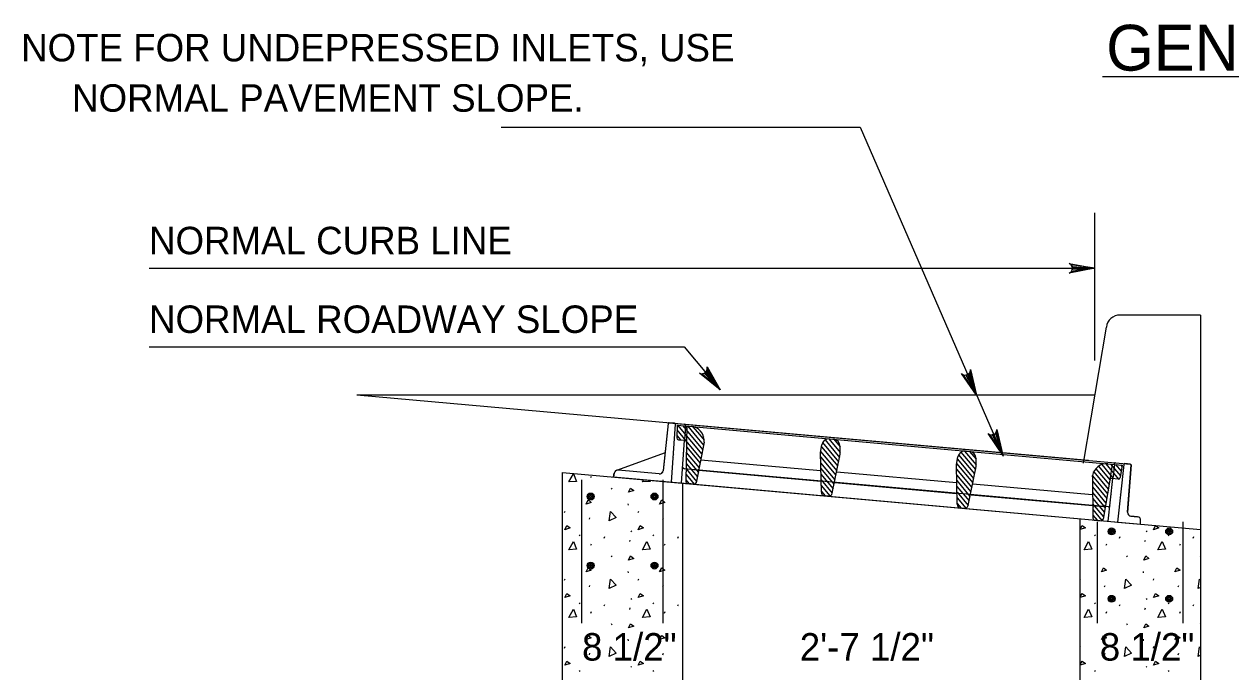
# Model space of a CAD drawing. Extents: x 6.91 to 13.84, y 0.35 to 9.99.
# Drawn here: x 6.908 to 9.548, y 3.739 to 5.155 of the extents above; entities that cross this region are included whole.
import ezdxf

# ---------------------------------------------------------------- set-up
doc = ezdxf.new("R2010")
doc.units = 0
for name, color, linetype in [('Default', 7, 'Continuous'), ('DETL-DIMS', 7, 'Continuous'), ('DETL-LINE', 7, 'Continuous'), ('DETL-NOTE', 7, 'Continuous')]:
    doc.layers.add(name, color=color, linetype=linetype)

msp = doc.modelspace()

# ---------------------------------------------------------------- linework, layer by layer
at = {"layer": 'Default'}
for p, q in [((8.1477, 4.1641), (8.1493, 4.1673)), ((8.2609, 4.1544), (8.2636, 4.1595)), ((8.1924, 4.1411), (8.194, 4.1387)), ((8.2287, 4.1069), (8.2291, 4.1037)), ((8.0902, 4.0876), (8.0914, 4.0908)), ((8.1445, 4.0731), (8.1457, 4.0763)), ((8.2512, 4.0876), (8.2524, 4.0908)), ((8.3055, 4.0731), (8.3068, 4.0763)), ((8.2355, 4.0477), (8.2367, 4.0457)), ((9.3627, 4.0477), (9.3639, 4.0457)), ((8.1224, 4.0385), (8.124, 4.0365)), ((8.1477, 4.0159), (8.1493, 4.0192)), ((8.1767, 4.0316), (8.1783, 4.0349)), ((8.2327, 4.024), (8.2339, 4.0272)), ((8.2834, 4.0385), (8.285, 4.0365)), ((8.3088, 4.0159), (8.3104, 4.0192)), ((8.3378, 4.0316), (8.3394, 4.0349)), ((9.2496, 4.0385), (9.2512, 4.0365)), ((9.2749, 4.0159), (9.2766, 4.0192)), ((9.3039, 4.0316), (9.3055, 4.0349)), ((9.3599, 4.024), (9.3611, 4.0272)), ((9.4106, 4.0385), (9.4122, 4.0365)), ((9.436, 4.0159), (9.4376, 4.0192)), ((9.465, 4.0316), (9.4666, 4.0349)), ((8.1924, 3.993), (8.194, 3.9906)), ((9.3196, 3.993), (9.3212, 3.9906)), ((9.4807, 3.993), (9.4813, 3.992)), ((8.0902, 3.9394), (8.0914, 3.9427)), ((8.2287, 3.9588), (8.2291, 3.9555)), ((8.2512, 3.9394), (8.2524, 3.9427)), ((9.2184, 3.9421), (9.2186, 3.9427)), ((9.3559, 3.9588), (9.3563, 3.9555)), ((9.3784, 3.9394), (9.3796, 3.9427)), ((8.1445, 3.9249), (8.1457, 3.9282)), ((8.3055, 3.9249), (8.3068, 3.9282)), ((9.2717, 3.9249), (9.2729, 3.9282)), ((9.4328, 3.9249), (9.434, 3.9282)), ((9.4813, 3.9237), (9.4762, 3.9213)), ((8.1224, 3.8903), (8.124, 3.8883)), ((8.1767, 3.8835), (8.1783, 3.8867)), ((8.2355, 3.8996), (8.2367, 3.8976)), ((8.2834, 3.8903), (8.285, 3.8883)), ((8.3378, 3.8835), (8.3394, 3.8867)), ((9.2496, 3.8903), (9.2512, 3.8883)), ((9.3039, 3.8835), (9.3055, 3.8867)), ((9.3627, 3.8996), (9.3639, 3.8976)), ((9.4106, 3.8903), (9.4122, 3.8883)), ((9.465, 3.8835), (9.4666, 3.8867)), ((8.1477, 3.8678), (8.1493, 3.871)), ((8.2327, 3.8758), (8.2339, 3.8791)), ((8.3088, 3.8678), (8.3104, 3.871)), ((9.2749, 3.8678), (9.2766, 3.871)), ((9.3599, 3.8758), (9.3611, 3.8791)), ((9.436, 3.8678), (9.4376, 3.871)), ((8.1924, 3.8448), (8.194, 3.8424)), ((9.3196, 3.8448), (9.3212, 3.8424)), ((9.4807, 3.8448), (9.4813, 3.8439)), ((8.2287, 3.8106), (8.2291, 3.8074)), ((9.3559, 3.8106), (9.3563, 3.8074)), ((8.0902, 3.7913), (8.0914, 3.7945)), ((8.1445, 3.7768), (8.1457, 3.78)), ((8.2512, 3.7913), (8.2524, 3.7945)), ((8.3055, 3.7768), (8.3068, 3.78)), ((9.2184, 3.794), (9.2186, 3.7945)), ((9.2717, 3.7768), (9.2729, 3.78)), ((9.3784, 3.7913), (9.3796, 3.7945)), ((9.4328, 3.7768), (9.434, 3.78)), ((9.4813, 3.7756), (9.4762, 3.7732)), ((8.2355, 3.7514), (8.2367, 3.7494)), ((9.3627, 3.7514), (9.3639, 3.7494)), ((8.1224, 3.7422), (8.124, 3.7402)), ((8.2834, 3.7422), (8.285, 3.7402)), ((9.2496, 3.7422), (9.2512, 3.7402)), ((9.4106, 3.7422), (9.4122, 3.7402))]:
    msp.add_line(p, q, dxfattribs=at)
for points in [[(8.0998, 4.1544), (8.1095, 4.1725), (8.1167, 4.1556), (8.0998, 4.1544)], [(8.2766, 4.1583), (8.2778, 4.1556), (8.2609, 4.1544)], [(8.2303, 4.1319), (8.2343, 4.1407), (8.2415, 4.1355), (8.2303, 4.1319)], [(8.1373, 4.1061), (8.1417, 4.115), (8.1485, 4.1097), (8.1373, 4.1061)], [(8.2983, 4.1061), (8.3027, 4.115), (8.3096, 4.1097), (8.2983, 4.1061)], [(8.188, 4.0695), (8.1908, 4.09), (8.2033, 4.0767), (8.188, 4.0695)], [(8.0906, 4.0501), (8.095, 4.059), (8.1022, 4.0538), (8.0906, 4.0501)], [(8.2516, 4.0501), (8.256, 4.059), (8.2633, 4.0538), (8.2516, 4.0501)], [(9.2184, 4.0513), (9.2222, 4.059), (9.2295, 4.0538), (9.2184, 4.0503)], [(9.3788, 4.0501), (9.3832, 4.059), (9.3905, 4.0538), (9.3788, 4.0501)], [(8.0998, 4.0063), (8.1095, 4.0244), (8.1167, 4.0075), (8.0998, 4.0063)], [(8.2609, 4.0063), (8.2705, 4.0244), (8.2778, 4.0075), (8.2609, 4.0063)], [(9.227, 4.0063), (9.2367, 4.0244), (9.2439, 4.0075), (9.227, 4.0063)], [(9.3881, 4.0063), (9.3977, 4.0244), (9.405, 4.0075), (9.3881, 4.0063)], [(8.2303, 3.9837), (8.2343, 3.9926), (8.2415, 3.9873), (8.2303, 3.9837)], [(9.3575, 3.9837), (9.3615, 3.9926), (9.3687, 3.9873), (9.3575, 3.9837)], [(8.1373, 3.958), (8.1417, 3.9668), (8.1485, 3.9616), (8.1373, 3.958)], [(8.2983, 3.958), (8.3027, 3.9668), (8.3096, 3.9616), (8.2983, 3.958)], [(9.2645, 3.958), (9.2689, 3.9668), (9.2757, 3.9616), (9.2645, 3.958)], [(9.4255, 3.958), (9.4299, 3.9668), (9.4368, 3.9616), (9.4255, 3.958)], [(8.188, 3.9213), (8.1908, 3.9419), (8.2033, 3.9286), (8.188, 3.9213)], [(9.3152, 3.9213), (9.318, 3.9419), (9.3305, 3.9286), (9.3152, 3.9213)], [(9.4762, 3.9213), (9.479, 3.9419), (9.4813, 3.9394)], [(8.0906, 3.902), (8.095, 3.9109), (8.1022, 3.9056), (8.0906, 3.902)], [(8.2516, 3.902), (8.256, 3.9109), (8.2633, 3.9056), (8.2516, 3.902)], [(9.2184, 3.9032), (9.2222, 3.9109), (9.2295, 3.9056), (9.2184, 3.9022)], [(9.3788, 3.902), (9.3832, 3.9109), (9.3905, 3.9056), (9.3788, 3.902)], [(8.0998, 3.8581), (8.1095, 3.8762), (8.1167, 3.8593), (8.0998, 3.8581)], [(8.2609, 3.8581), (8.2705, 3.8762), (8.2778, 3.8593), (8.2609, 3.8581)], [(9.227, 3.8581), (9.2367, 3.8762), (9.2439, 3.8593), (9.227, 3.8581)], [(9.3881, 3.8581), (9.3977, 3.8762), (9.405, 3.8593), (9.3881, 3.8581)], [(8.2303, 3.8356), (8.2343, 3.8444), (8.2415, 3.8392), (8.2303, 3.8356)], [(9.3575, 3.8356), (9.3615, 3.8444), (9.3687, 3.8392), (9.3575, 3.8356)], [(8.1373, 3.8098), (8.1417, 3.8187), (8.1485, 3.8134), (8.1373, 3.8098)], [(8.2983, 3.8098), (8.3027, 3.8187), (8.3096, 3.8134), (8.2983, 3.8098)], [(9.2645, 3.8098), (9.2689, 3.8187), (9.2757, 3.8134), (9.2645, 3.8098)], [(9.4255, 3.8098), (9.4299, 3.8187), (9.4368, 3.8134), (9.4255, 3.8098)], [(8.188, 3.7732), (8.1908, 3.7937), (8.2033, 3.7804), (8.188, 3.7732)], [(9.3152, 3.7732), (9.318, 3.7937), (9.3305, 3.7804), (9.3152, 3.7732)], [(9.4762, 3.7732), (9.479, 3.7937), (9.4813, 3.7913)], [(8.0906, 3.7539), (8.095, 3.7627), (8.1022, 3.7575), (8.0906, 3.7539)], [(8.2516, 3.7539), (8.256, 3.7627), (8.2633, 3.7575), (8.2516, 3.7539)], [(9.2184, 3.7551), (9.2222, 3.7627), (9.2295, 3.7575), (9.2184, 3.754)], [(9.3788, 3.7539), (9.3832, 3.7627), (9.3905, 3.7575), (9.3788, 3.7539)]]:
    msp.add_lwpolyline(points, dxfattribs=at)
at = {"layer": 'DETL-DIMS'}
for p, q in [((7.9515, 4.9299), (8.737, 4.9299)), ((8.737, 4.9299), (9.0498, 4.2111)), ((9.2505, 4.42), (9.2505, 4.7428)), ((7.1813, 4.6215), (9.2505, 4.6215)), ((7.1813, 4.4494), (8.3517, 4.4494)), ((8.3517, 4.4494), (8.4303, 4.356))]:
    msp.add_line(p, q, dxfattribs=at)
for points in [[(9.2505, 4.6215), (9.194, 4.6109), (9.1983, 4.6139), (9.2006, 4.6177), (9.2012, 4.6215), (9.2006, 4.6253), (9.1983, 4.629), (9.194, 4.6321), (9.2505, 4.6215), (9.1983, 4.629), (9.2006, 4.6253), (9.2505, 4.6215), (9.2012, 4.6215), (9.2006, 4.6177), (9.2505, 4.6215), (9.1983, 4.6139)], [(8.4303, 4.356), (8.3858, 4.3924), (8.3909, 4.391), (8.3953, 4.3918), (8.3986, 4.3937), (8.4011, 4.3966), (8.4025, 4.4008), (8.402, 4.4061), (8.4303, 4.356), (8.4025, 4.4008), (8.4011, 4.3966), (8.4303, 4.356), (8.3986, 4.3937), (8.3953, 4.3918), (8.4303, 4.356), (8.3909, 4.391)], [(8.9911, 4.3438), (8.9588, 4.3914), (8.9633, 4.3886), (8.9677, 4.3881), (8.9714, 4.389), (8.9746, 4.3911), (8.9772, 4.3947), (8.9783, 4.3999), (8.9911, 4.3438), (8.9772, 4.3947), (8.9746, 4.3911), (8.9911, 4.3438), (8.9714, 4.389), (8.9677, 4.3881), (8.9911, 4.3438), (8.9633, 4.3886)], [(9.0491, 4.2128), (9.0168, 4.2605), (9.0213, 4.2577), (9.0257, 4.2571), (9.0294, 4.258), (9.0326, 4.2601), (9.0352, 4.2637), (9.0362, 4.2689), (9.0491, 4.2128), (9.0352, 4.2637), (9.0326, 4.2601), (9.0491, 4.2128), (9.0294, 4.258), (9.0257, 4.2571), (9.0491, 4.2128), (9.0213, 4.2577)]]:
    msp.add_lwpolyline(points, dxfattribs=at)
at = {"layer": 'DETL-LINE'}
for p, q in [((9.4813, 4.5192), (9.3055, 4.5192)), ((9.4813, 4.5192), (9.4813, 2.6989)), ((9.2256, 4.1954), (9.2755, 4.4929)), ((7.6359, 4.3449), (9.2364, 4.202)), ((7.6359, 4.3449), (9.2506, 4.3449)), ((8.317, 4.2822), (8.3057, 4.1789)), ((8.317, 4.2822), (8.3058, 4.1791)), ((8.3309, 4.2829), (8.3191, 4.2839)), ((8.3191, 4.2839), (9.3277, 4.1936)), ((8.3242, 4.1539), (8.3327, 4.2808)), ((8.3376, 4.2783), (8.3681, 4.2419)), ((8.3487, 4.2773), (8.3738, 4.2473)), ((8.355, 4.2768), (8.3529, 4.2456)), ((8.355, 4.2768), (8.3552, 4.2788)), ((8.3576, 4.2765), (8.3568, 4.2416)), ((8.3358, 4.2561), (8.344, 4.2464)), ((8.3361, 4.268), (8.3624, 4.2365)), ((8.3597, 4.2764), (8.3795, 4.2526)), ((8.3709, 4.2751), (8.3852, 4.258)), ((8.3795, 4.2526), (8.3944, 4.2348)), ((8.3852, 4.258), (8.3957, 4.2455)), ((8.3464, 4.152), (8.3529, 4.2456)), ((8.3567, 4.2312), (8.3867, 4.1952)), ((8.3624, 4.2365), (8.3886, 4.2051)), ((8.3681, 4.2419), (8.3905, 4.215)), ((8.3738, 4.2473), (8.3925, 4.2249)), ((8.6522, 4.2311), (8.6877, 4.1886)), ((8.6546, 4.2404), (8.6897, 4.1984)), ((8.66, 4.2461), (8.6917, 4.2082)), ((8.6682, 4.2486), (8.6931, 4.2187)), ((8.679, 4.2477), (8.6931, 4.2309)), ((8.31, 4.218), (8.2042, 4.1796)), ((8.3564, 4.2071), (8.3829, 4.1754)), ((8.3565, 4.2191), (8.3848, 4.1853)), ((8.6502, 4.2091), (8.6837, 4.1691)), ((8.6504, 4.2211), (8.6857, 4.1788)), ((8.9496, 4.2045), (8.9851, 4.162)), ((8.952, 4.2137), (8.9871, 4.1718)), ((8.9574, 4.2195), (8.9891, 4.1815)), ((8.9655, 4.2219), (8.9905, 4.192)), ((8.9764, 4.2211), (8.9905, 4.2042)), ((8.0857, 2.6989), (8.0857, 4.1753)), ((8.0857, 4.1753), (9.4813, 4.0507)), ((8.1976, 4.1653), (8.1991, 4.1737)), ((8.2973, 4.172), (8.2075, 4.1801)), ((8.2973, 4.172), (8.2075, 4.1801)), ((8.3598, 4.1822), (8.3523, 4.1828)), ((8.356, 4.171), (8.374, 4.1495)), ((8.3562, 4.183), (8.379, 4.1556)), ((8.3563, 4.195), (8.3809, 4.1655)), ((9.2696, 4.1007), (8.3598, 4.1822)), ((8.3802, 4.1803), (8.3598, 4.1822)), ((8.6505, 4.1965), (8.6817, 4.1593)), ((8.6508, 4.184), (8.6796, 4.1495)), ((8.6511, 4.1714), (8.6776, 4.1397)), ((8.9476, 4.1824), (8.981, 4.1424)), ((8.9478, 4.1944), (8.9831, 4.1522)), ((9.248, 4.1765), (9.2797, 4.1386)), ((9.2525, 4.1833), (9.2814, 4.1488)), ((9.2583, 4.1886), (9.2831, 4.1588)), ((9.2654, 4.1923), (9.2911, 4.1615)), ((9.2741, 4.1941), (9.302, 4.1607)), ((9.2885, 4.1932), (9.2831, 4.1586)), ((9.2848, 4.1935), (9.3061, 4.168)), ((9.2933, 4.1927), (9.2899, 4.1616)), ((9.2933, 4.1927), (9.2935, 4.1947)), ((9.2958, 4.1925), (9.3077, 4.1782)), ((9.3138, 4.1929), (9.2996, 4.0666)), ((9.3138, 4.1929), (9.2996, 4.0666)), ((9.3068, 4.1915), (9.3093, 4.1885)), ((9.3277, 4.1936), (9.3159, 4.1946)), ((9.322, 4.0881), (9.3294, 4.1915)), ((9.3294, 4.1915), (9.322, 4.0879)), ((8.1281, 3.8456), (8.1281, 4.1591)), ((8.1976, 4.1653), (9.3502, 4.062)), ((8.3063, 3.8456), (8.3063, 4.1591)), ((8.3487, 2.8202), (8.3487, 4.1519)), ((8.3559, 4.1589), (8.363, 4.1505)), ((8.6514, 4.1589), (8.6756, 4.1299)), ((8.6517, 4.1463), (8.6706, 4.1237)), ((8.9479, 4.1698), (8.979, 4.1326)), ((8.9482, 4.1573), (8.977, 4.1228)), ((8.9485, 4.1447), (8.975, 4.113)), ((9.2449, 4.1558), (9.2762, 4.1183)), ((9.2451, 4.1677), (9.2779, 4.1285)), ((9.2797, 4.0684), (9.2899, 4.1616)), ((8.652, 4.1338), (8.6603, 4.1238)), ((8.9488, 4.1322), (8.973, 4.1032)), ((8.9491, 4.1196), (8.9679, 4.0971)), ((9.2451, 4.1434), (9.2745, 4.1082)), ((9.2452, 4.1311), (9.2728, 4.0981)), ((9.2454, 4.1187), (9.2711, 4.0879)), ((8.9494, 4.1071), (8.9577, 4.0972)), ((9.2452, 4.1028), (9.2491, 4.1025)), ((9.2455, 4.1063), (9.2694, 4.0778)), ((9.2457, 4.0939), (9.2658, 4.0699)), ((9.2491, 4.1025), (9.2696, 4.1007)), ((9.2793, 4.0998), (9.2696, 4.1007)), ((9.2184, 2.8202), (9.2184, 4.0742)), ((9.2459, 4.0815), (9.255, 4.0706)), ((9.256, 3.8456), (9.256, 4.067)), ((9.3433, 4.0784), (9.3291, 4.0796)), ((9.3291, 4.0796), (9.3433, 4.0784)), ((9.3502, 4.062), (9.3504, 4.0704)), ((9.4437, 3.8456), (9.4437, 4.067))]:
    msp.add_line(p, q, dxfattribs=at)
for points in [[(8.1991, 4.1737), (8.1976, 4.1653), (8.3242, 4.1539), (8.3327, 4.2808)], [(9.2996, 4.0666), (9.3502, 4.062), (9.3504, 4.0704)]]:
    msp.add_lwpolyline(points, dxfattribs=at)
for centre, radius in [((8.1474, 4.1226), 0.00758), ((8.1474, 4.1226), 0.00569), ((8.1474, 4.1226), 0.00379), ((8.1474, 4.1226), 0.0019), ((8.287, 4.1226), 0.00758), ((8.287, 4.1226), 0.00569), ((8.287, 4.1226), 0.00379), ((8.287, 4.1226), 0.0019), ((9.2869, 4.0462), 0.00758), ((9.2869, 4.0462), 0.00569), ((9.2869, 4.0462), 0.00379), ((9.2869, 4.0462), 0.0019), ((9.4128, 4.0462), 0.00758), ((9.4128, 4.0462), 0.00569), ((9.4128, 4.0462), 0.00379), ((9.4128, 4.0462), 0.0019), ((8.1474, 3.9717), 0.00758), ((8.1474, 3.9717), 0.00569), ((8.1474, 3.9717), 0.00379), ((8.1474, 3.9717), 0.0019), ((8.287, 3.9717), 0.00758), ((8.287, 3.9717), 0.00569), ((8.287, 3.9717), 0.00379), ((8.287, 3.9717), 0.0019), ((9.2869, 3.899), 0.00758), ((9.2869, 3.899), 0.00569), ((9.2869, 3.899), 0.00379), ((9.2869, 3.899), 0.0019), ((9.4128, 3.899), 0.00758), ((9.4128, 3.899), 0.00569), ((9.4128, 3.899), 0.00379), ((9.4128, 3.899), 0.0019)]:
    msp.add_circle(centre, radius, dxfattribs=at)
for centre, radius, start, end in [((9.3055, 4.4888), 0.0303, 90, 172.2341), ((8.3189, 4.282), 0.00195, 84.8815, 173.7719), ((8.3189, 4.282), 0.00195, 84.8815, 173.7719), ((8.3307, 4.2809), 0.00195, 356.1793, 84.8815), ((8.3307, 4.2809), 0.00195, 356.1793, 84.8815), ((8.3532, 4.2789), 0.00195, 356.0273, 84.8815), ((8.2068, 4.1723), 0.00782, 84.8755, 169.8815), ((8.2068, 4.1723), 0.00782, 84.8815, 169.8815), ((8.298, 4.1798), 0.00782, 264.8755, 354.4477), ((8.298, 4.1798), 0.00782, 264.8815, 353.0961), ((8.3527, 4.1867), 0.00391, 176.0273, 264.8815), ((8.3601, 4.186), 0.00391, 178.6956, 264.8815), ((8.3806, 4.1842), 0.00391, 264.8815, 349.8815), ((9.2955, 4.1945), 0.00195, 84.8815, 173.7484), ((9.3157, 4.1927), 0.00195, 84.8815, 173.5837), ((9.3157, 4.1927), 0.00195, 84.8815, 173.5837), ((9.3275, 4.1916), 0.00195, 355.8908, 84.8815), ((9.3275, 4.1916), 0.00195, 355.8908, 84.8815), ((9.2495, 4.1064), 0.00391, 179.8815, 264.8815), ((9.2699, 4.1045), 0.00391, 264.8815, 351.0675), ((9.2796, 4.1037), 0.00391, 264.8815, 353.7358), ((9.3298, 4.0874), 0.00782, 175.1145, 264.8815), ((9.3298, 4.0874), 0.00782, 176.667, 264.8815), ((9.3426, 4.0706), 0.00782, 358.4238, 84.8815), ((9.3426, 4.0706), 0.00782, 358.4238, 84.8815)]:
    msp.add_arc(centre, radius, start, end, dxfattribs=at)
at = {"layer": 'DETL-NOTE'}
for p, q in [((9.2669, 5.0407), (10.5175, 5.0407)), ((8.3363, 4.2784), (8.3357, 4.2508)), ((8.3363, 4.2784), (9.3097, 4.1913)), ((8.3363, 4.2784), (8.3363, 4.2784)), ((8.3968, 4.2537), (8.3968, 4.2537)), ((8.3393, 4.2468), (8.3532, 4.2455)), ((8.3393, 4.2468), (8.3393, 4.2468)), ((8.3568, 4.2416), (8.3559, 4.1548)), ((8.3957, 4.2417), (8.3784, 4.1527)), ((8.3957, 4.2417), (8.3957, 4.2445)), ((8.65, 4.219), (8.653, 4.2358)), ((8.6931, 4.2151), (8.6931, 4.2322)), ((8.329, 4.2079), (8.329, 4.2079)), ((8.3305, 4.2135), (8.3305, 4.2135)), ((8.3491, 4.2117), (8.3491, 4.2117)), ((8.3524, 4.2183), (8.3524, 4.2183)), ((8.3882, 4.2031), (8.6503, 4.1797)), ((8.6521, 4.1318), (8.65, 4.219)), ((8.6756, 4.1297), (8.6931, 4.2151)), ((8.9474, 4.1923), (8.9504, 4.2091)), ((8.9905, 4.1885), (8.9905, 4.2055)), ((8.3591, 4.1908), (8.3591, 4.1908)), ((8.3806, 4.1767), (8.3806, 4.1767)), ((8.3837, 4.18), (8.6504, 4.1561)), ((8.6859, 4.1765), (8.9476, 4.153)), ((8.9494, 4.1051), (8.9474, 4.1923)), ((8.973, 4.103), (8.9905, 4.1885)), ((8.9905, 4.1885), (8.9905, 4.1885)), ((9.2458, 4.1777), (9.2458, 4.1777)), ((9.3097, 4.1913), (9.3054, 4.1639)), ((9.3277, 4.1936), (9.3277, 4.1936)), ((8.1976, 4.1653), (8.1976, 4.1653)), ((8.3242, 4.1539), (8.3242, 4.1539)), ((8.3742, 4.1495), (8.3594, 4.1508)), ((8.3594, 4.1508), (8.3594, 4.1508)), ((8.6815, 4.1533), (8.947, 4.1295)), ((9.2447, 4.1264), (8.9833, 4.1499)), ((9.2448, 4.1657), (9.2453, 4.1684)), ((9.2448, 4.1657), (9.2459, 4.075)), ((9.2448, 4.1657), (9.2448, 4.1657)), ((9.2831, 4.1586), (9.2685, 4.073)), ((9.3012, 4.1606), (9.2873, 4.1619)), ((9.3104, 4.1552), (9.3104, 4.1552)), ((8.6672, 4.1232), (8.6592, 4.1239)), ((8.9797, 4.1266), (9.2452, 4.1028)), ((9.2833, 4.1349), (9.2833, 4.1349)), ((9.2875, 4.1276), (9.2875, 4.1276)), ((9.3039, 4.1263), (9.3039, 4.1263)), ((9.3044, 4.1206), (9.3044, 4.1206)), ((8.9646, 4.0966), (8.9566, 4.0973)), ((9.2481, 4.099), (9.2481, 4.099)), ((9.2718, 4.109), (9.2718, 4.109)), ((9.306, 4.1054), (9.306, 4.1054)), ((9.3216, 4.104), (9.3216, 4.104)), ((9.2495, 4.0711), (9.2643, 4.0697)), ((9.3433, 4.0784), (9.3433, 4.0784)), ((9.3502, 4.062), (9.3502, 4.062))]:
    msp.add_line(p, q, dxfattribs=at)
for centre, radius, start, end in [((8.3396, 4.2507), 0.00391, 178.6956, 264.8815), ((8.3645, 4.2445), 0.0313, 359.8815, 84.8815), ((8.3529, 4.2416), 0.00391, 358.6956, 84.8815), ((8.6684, 4.233), 0.0156, 84.8815, 169.8815), ((8.6775, 4.2322), 0.0156, 359.8815, 84.8815), ((8.9658, 4.2064), 0.0156, 84.8815, 169.8815), ((8.9749, 4.2055), 0.0156, 359.8815, 84.8815), ((9.276, 4.1629), 0.0313, 84.8815, 169.8815), ((8.3598, 4.1547), 0.00391, 178.6956, 264.8815), ((8.3746, 4.1533), 0.00391, 264.8815, 349.8815), ((9.2869, 4.158), 0.00391, 84.8815, 171.0675), ((9.3016, 4.1645), 0.00391, 264.8815, 351.0675), ((8.6599, 4.1317), 0.00782, 179.6452, 264.8815), ((8.6679, 4.131), 0.00782, 264.8815, 350.1179), ((8.9573, 4.1051), 0.00782, 179.6452, 264.8815), ((8.9653, 4.1044), 0.00782, 264.8815, 350.1179), ((9.2499, 4.0749), 0.00391, 179.8815, 264.8815), ((9.2647, 4.0736), 0.00391, 264.8815, 351.0675)]:
    msp.add_arc(centre, radius, start, end, dxfattribs=at)

# ---------------------------------------------------------------- texts
for s, height, p in [('GENERAL NOTES', 0.100117, (9.2751, 5.0534)), ('NOTE FOR UNDEPRESSED INLETS, USE', 0.06, (6.9015, 5.0736)), ('     NORMAL PAVEMENT SLOPE. ', 0.06, (6.9015, 4.9636)), ('NORMAL CURB LINE', 0.06, (7.1813, 4.6521)), ('NORMAL ROADWAY SLOPE', 0.06, (7.1813, 4.4801)), ('8 1/2"', 0.06, (8.1285, 3.764)), ('2\'-7 1/2"', 0.06, (8.6048, 3.764)), ('8 1/2"', 0.06, (9.2611, 3.764))]:
    msp.add_text(s, height=height, dxfattribs=at).set_placement(p)

doc.saveas('drawing.dxf')
